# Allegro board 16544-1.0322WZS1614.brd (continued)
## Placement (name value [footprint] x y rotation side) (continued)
PC259  SC68P50V2JN-1GP  [C402H22]  139.19 74.17 90 top
PC260  SC10U6D3V3MX-DL-GP  [C603H36]  136.27 74.3 270 top
PC261  SC10U6D3V3MX-DL-GP  [C603H36]  136.27 75.56 270 top
PC262  SC1U50V3KX-1-GP  [C603H36]  130.53 128.19 270 top
PC263  SC10U6D3V3MX-DL-GP  [C603H36]  134.34 130.73 90 top
PC265  SC68P50V2JN-1GP  [C402H22]  141.07 128.83 90 top
PC266  SC10U6D3V3MX-DL-GP  [C603H36]  137.52 132 270 top
PC267  SC10U6D3V3MX-DL-GP  [C603H36]  137.52 130.73 270 top
PC268  SC1U50V3KX-1-GP  [C603H36]  122.43 200.91 270 top
PC269  SC1U10V2KX-1DLGP  [C402H22]  122.3 211.58 270 top
PC270  SC10U6D3V3MX-DL-GP  [C603H36]  122.43 210.44 270 top
PC271  SC10U6D3V3MX-DL-GP  [C603H36]  128.02 210.57 90 top
PC272  SC1U10V2KX-1DLGP  [C402H22]  124.33 214.12 270 top
PC274  SC4D7U6D3V3KX-DLGP  [C603H36]  113.02 150.09 90 bottom
PC275  SC4D7U6D3V3KX-DLGP  [C603H36]  111.91 154.46 270 top
PC276  SC1U10V2KX-1DLGP  [C402H22]  105.1 144.41 0 top
PC277  SCD1U25V2KX-1-DL-GP  [C402H22]  121.94 139.66 0 top
PC278  SCD01U50V2KX-1DLGP  [C402H22]  116.18 145.99 0 bottom
PC279  SCD22U25V3KX-DL-GP  [C603H36]  121.6 142.2 180 top
PC280  SCD22U25V3KX-DL-GP  [C603H36]  124.58 143.12 270 top
PC281  SCD1U25V2KX-1-DL-GP  [C402H22]  123.18 141.06 270 top
PC282  SCD22U25V3KX-DL-GP  [C603H36]  124.47 146.37 0 top
PC283  SCD1U25V2KX-1-DL-GP  [C402H22]  125.53 144.87 0 top
PC284  SCD22U25V3KX-DL-GP  [C603H36]  123.02 150.33 180 top
PC285  SCD1U25V2KX-1-DL-GP  [C402H22]  125.53 148.73 0 top
PC286  SCD1U25V2KX-1-DL-GP  [C402H22]  125.22 152.02 0 top
PC287  SC4700P50V2KX-1DLGP  [C402H22]  117.04 154.34 0 top
PC288  SCD22U25V3KX-DL-GP  [C603H36]  123.99 154.04 180 top
PC289  SCD1U25V2KX-1-DL-GP  [C402H22]  118.49 155.96 90 top
PC290  SCD1U25V2KX-1-DL-GP  [C402H22]  116.11 150.13 180 bottom
PC291  SCD1U25V2KX-1-DL-GP  [C402H22]  125.22 155.83 0 top
PC292  SCD22U25V3KX-DL-GP  [C603H36]  124.02 156.73 180 top
PC293  SCD1U25V2KX-1-DL-GP  [C402H22]  120.68 152.29 180 bottom
PC294  SCD22U25V3KX-DL-GP  [C603H36]  119.65 153.4 0 bottom
PC295  SC4700P50V2KX-1DLGP  [C402H22]  119.33 141.72 180 top
PC296  SCD1U25V2KX-1-DL-GP  [C402H22]  119.99 139.64 0 top
PC297  SCD1U25V2KX-1-DL-GP  [C402H22]  117.17 145.91 0 bottom
PC298  SC470P50V2KX-3DLGP  [C402H22]  115.65 154.58 90 bottom
PC299  SC470P50V2KX-3DLGP  [C402H22]  115.98 157.53 270 top
PC300  SC470P50V2KX-3DLGP  [C402H22]  112.01 151.18 270 bottom
PC301  SC470P50V2KX-3DLGP  [C402H22]  112.55 156.79 270 bottom
PC304  SC10U25V5KX-L-GP  [C805H56]  98.58 112.88 90 bottom
PC306  SC10U25V5KX-L-GP  [C805H56]  64.26 113.28 270 bottom
PC307  SC1U10V2KX-1DLGP  [C402H22]  95.66 120.73 90 bottom
PC308  SC1U10V2KX-1DLGP  [C402H22]  58.75 120.8 90 bottom
PC309  SCD22U25V3KX-DL-GP  [C603H36]  97.38 118.39 270 bottom
PC310  SC1KP50V2KX-1DLGP  [C402H22]  105.66 123.8 0 top
PC311  SCD22U25V3KX-DL-GP  [C603H36]  60.43 118.41 270 bottom
PC312  SC1KP50V2KX-1DLGP  [C402H22]  68.78 122.91 0 top
PC313  SC1U50V3KX-1-GP  [C603H36]  90.17 115.14 270 bottom
PC314  SC1U50V3KX-1-GP  [C603H36]  54.51 112.78 90 top
PC315  SC10U25V5KX-L-GP  [C805H56]  48.54 112.83 270 top
PC316  SC10U25V5KX-L-GP  [C805H56]  86.11 113.28 90 bottom
PC317  SC22U6D3V5MX-2DLGP  [C805H54]  92.46 148.79 270 bottom
PC318  SC22U6D3V5MX-2DLGP  [C805H54]  35.62 149.31 270 top
PC319  SC22U6D3V5MX-2DLGP  [C805H54]  35.62 147.25 270 top
PC320  SC22U6D3V5MX-2DLGP  [C805H54]  35.59 145.24 270 top
PC321  SC22U6D3V5MX-2DLGP  [C805H54]  83 152.65 270 bottom
PC322  SC22U6D3V5MX-2DLGP  [C805H54]  87.55 148.8 90 bottom
PC323  SC22U6D3V5MX-2DLGP  [C805H54]  87.56 152.69 90 bottom
PC324  SC22U6D3V5MX-2DLGP  [C805H54]  92.46 150.72 270 bottom
PC325  SC22U6D3V5MX-2DLGP  [C805H54]  83.01 150.64 270 bottom
PC326  SC22U6D3V5MX-2DLGP  [C805H54]  83.13 151.63 90 top
PC327  SC1U10V2KX-1DLGP  [C402H22]  84.15 120.98 90 bottom
PC328  SC1U10V2KX-1DLGP  [C402H22]  47.85 120.83 90 bottom
PC329  SCD22U25V3KX-DL-GP  [C603H36]  49.22 118.44 270 bottom
PC330  SCD22U25V3KX-DL-GP  [C603H36]  85.92 118.39 270 bottom
PC331  SC1KP50V2KX-1DLGP  [C402H22]  56.95 122.56 0 top
PC332  SC1KP50V2KX-1DLGP  [C402H22]  93.93 122.53 0 top
PC333  SC22U6D3V5MX-2DLGP  [C805H54]  83.13 153.61 90 top
PC334  SC22U6D3V5MX-2DLGP  [C805H54]  87.69 153.19 270 top
PC335  SC22U6D3V5MX-2DLGP  [C805H54]  87.69 151.26 270 top
PC336  SC22U6D3V5MX-2DLGP  [C805H54]  77.72 151.62 90 bottom
PC337  SC22U6D3V5MX-2DLGP  [C805H54]  83.13 147.7 90 top
PC338  SC22U6D3V5MX-2DLGP  [C805H54]  83.13 149.63 90 top
PC339  SC22U6D3V5MX-2DLGP  [C805H54]  87.68 149.31 270 top
PC340  SC22U6D3V5MX-2DLGP  [C805H54]  87.68 147.38 270 top
PC341  SC22U6D3V5MX-2DLGP  [C805H54]  77.65 152.05 270 top
PC342  SC22U6D3V5MX-2DLGP  [C805H54]  77.65 149.87 270 top
PC344  SC10U25V5KX-L-GP  [C805H56]  78.23 113.28 270 bottom
PC345  SC1U50V3KX-1-GP  [C603H36]  43 112.6 90 top
PC346  SC10U25V5KX-L-GP  [C805H56]  37.01 112.95 270 top
PC347  SC22U6D3V5MX-2DLGP  [C805H54]  77.65 147.71 270 top
PC348  SC22U6D3V5MX-2DLGP  [C805H54]  35.59 143.24 270 top
PC349  SC22U6D3V5MX-2DLGP  [C805H54]  35.59 141.31 270 top
PC350  SC22U6D3V5MX-2DLGP  [C805H54]  83.01 148.71 270 bottom
PC351  SC22U6D3V5MX-2DLGP  [C805H54]  87.55 150.73 90 bottom
PC352  SC22U6D3V5MX-2DLGP  [C805H54]  75.53 179.37 180 bottom
PC353  SC22U6D3V5MX-2DLGP  [C805H54]  92.46 147.64 90 top
PC354  SC22U6D3V5MX-2DLGP  [C805H54]  92.46 149.58 90 top
PC355  SC22U6D3V5MX-2DLGP  [C805H54]  92.46 151.51 90 top
PC356  SC22U6D3V5MX-2DLGP  [C805H54]  92.46 153.44 90 top
PC357  SC1U10V2KX-1DLGP  [C402H22]  72.28 119.79 0 top
PC358  SC1U10V2KX-1DLGP  [C402H22]  35.74 120.33 270 top
PC359  SCD22U25V3KX-DL-GP  [C603H36]  74.97 118.69 270 bottom
PC360  SCD22U25V3KX-DL-GP  [C603H36]  37.99 118.44 270 bottom
PC361  SC1KP50V2KX-1DLGP  [C402H22]  82.47 122.66 0 top
PC362  SC1KP50V2KX-1DLGP  [C402H22]  46.18 122.07 0 top
PC363  SC1U50V3KX-1-GP  [C603H36]  145.31 225.55 90 bottom
PC364  SC10U25V5KX-DL-GP  [C805H58]  145.19 223.9 90 bottom
PC365  SC1U10V2KX-1DLGP  [C402H22]  137.67 215.9 0 top
PC366  SC22U6D3V5MX-2DLGP  [C805H54]  116.31 214.88 0 top
PC367  SCD22U25V3KX-DL-GP  [C603H36]  137.08 215.98 180 bottom
PC368  SC22U6D3V5MX-2DLGP  [C805H54]  118.26 214.87 0 top
PC369  SC22U6D3V5MX-2DLGP  [C805H54]  118.57 218.83 180 bottom
PC370  SC22U6D3V5MX-2DLGP  [C805H54]  116.48 218.81 180 bottom
PC371  SC1KP50V2KX-1DLGP  [C402H22]  135.2 228.3 90 top
PC372  SC2D2U10V3KX-1DLGP-U  [C603H36]  119.51 204.17 270 bottom
PC373  SCD1U25V2KX-1-DL-GP  [C402H22]  112.83 202.59 0 bottom
PC374  SC1U10V2KX-1DLGP  [C402H22]  121.28 204.72 180 bottom
PC375  SC22U6D3V5MX-2DLGP  [C805H54]  119.96 194.97 270 bottom
PC376  SC22U6D3V5MX-2DLGP  [C805H54]  113.16 192.79 90 bottom
PC377  SC22U6D3V5MX-2DLGP  [C805H54]  119.91 196.95 270 bottom
PC378  SC22U6D3V5MX-2DLGP  [C805H54]  113.16 196.75 90 bottom
PC379  SC22U6D3V5MX-2DLGP  [C805H54]  113.16 194.82 90 bottom
PC380  SCD1U25V2KX-1-DL-GP  [C402H22]  111.1 206.07 270 top
PC381  SC10U25V5KX-DL-GP  [C805H58]  116.1 214.15 270 bottom
PC382  SC10U25V5KX-DL-GP  [C805H58]  110.31 205.08 90 bottom
PC383  SC470P50V2KX-3DLGP  [C402H22]  119.23 207.04 90 bottom
PC384  SC1U10V2KX-1DLGP  [C402H22]  14.55 210.67 90 top
PC385  SCD1U50V3KX-DL-GP  [C603H35]  10.82 215.98 0 top
PC386  SC22U6D3V5MX-2DLGP  [C805H54]  35.1 221.28 0 bottom
PC387  SC10U25V5KX-DL-GP  [C805H58]  13.61 218.44 180 bottom
PC388  SCD1U25V2KX-1-DL-GP  [C402H22]  15.6 223.6 0 bottom
PC389  SC22U6D3V5MX-2DLGP  [C805H54]  34.85 212.62 180 bottom
PC390  SC22U6D3V5MX-2DLGP  [C805H54]  31.34 212.62 0 top
PC391  SC22U6D3V5MX-2DLGP  [C805H54]  33.35 212.62 0 top
PC392  SC22U6D3V5MX-2DLGP  [C805H54]  33.12 221.28 0 bottom
PC393  SC22U6D3V5MX-2DLGP  [C805H54]  32.79 212.6 180 bottom
PC396  SC10U25V5KX-DL-GP  [C805H58]  15.6 218.44 180 bottom
PC397  SC18P50V2JN-1DLGP  [C402H22]  5.59 209.63 0 top
PC399  SC10U10V5KX-2DLGP  [C805H50]  135.71 23.37 0 bottom
PC400  SC10U10V5KX-2DLGP  [C805H50]  136.55 32.23 180 bottom
PC401  SC10U10V5KX-2DLGP  [C805H50]  130.56 32.23 180 bottom
PC405  SC22U6D3V5MX-2DLGP  [C805H54]  228.85 98.42 270 bottom
PC406  SC22U6D3V5MX-2DLGP  [C805H54]  228.85 100.46 270 bottom
PC407  SC22U6D3V5MX-2DLGP  [C805H54]  228.85 102.49 270 bottom
PC408  SC22U6D3V5MX-2DLGP  [C805H54]  228.85 104.52 270 bottom
PC409  SC4D7U6D3V3KX-DLGP  [C603H36]  106.17 144.19 0 top
PC410  SC22U6D3V5MX-2DLGP  [C805H54]  145.92 199.77 270 top
PC411  SC10U25V5KX-DL-GP  [C805H58]  153.16 224.51 90 top
PC412  SC10U25V5KX-DL-GP  [C805H58]  153.16 224.41 270 bottom
PC413  SC10U25V5KX-DL-GP  [C805H58]  13.61 218.44 0 top
PC414  SC10U25V5KX-DL-GP  [C805H58]  15.6 223.98 180 top
PC417  SC1U10V2KX-1DLGP  [C402H22]  142.19 216.92 0 bottom
PC418  SC1U50V3KX-1-GP  [C603H36]  135.33 208.03 180 top
PC419  SC10U6D3V3MX-DL-GP  [C603H36]  138.43 210.57 90 top
PC422  SC10U6D3V3MX-DL-GP  [C603H36]  145.8 208.79 180 top
PC423  SC10U6D3V3MX-DL-GP  [C603H36]  144.53 208.79 180 top
PC424  SC10U25V5KX-DL-GP  [C805H58]  112.14 17.17 180 top
PC425  SC10U25V5KX-DL-GP  [C805H58]  108.89 11.02 180 bottom
PC426  SCD1U25V2KX-1-DL-GP  [C402H22]  134.75 205.23 270 top
PC427  SC68P50V2JN-1GP  [C402H22]  144.53 204.98 0 top
PC428  SCD1U16V2KX-L-GP  [C402H22]  130.73 123.67 270 top
PC430  SCD47U25V3KX-1-DL-GP  [C603H36]  149.05 216.66 180 top
PC431  SCD47U25V3KX-1-DL-GP  [C603H36]  150.91 14.85 90 top
PC432  SCD1U16V2KX-L-GP  [C402H22]  142.98 64.82 0 top
PC433  SC1U50V3KX-1-GP  [C603H36]  138.73 65.2 90 top
PC437  SC10U25V5KX-DL-GP  [C805H58]  90.51 112.14 90 top
PC438  SC10U25V5KX-DL-GP  [C805H58]  90.49 110.14 90 top
PC439  SC10U25V5KX-DL-GP  [C805H58]  84.24 110.13 270 top
PC440  SC10U25V5KX-DL-GP  [C805H58]  84.24 112.14 270 top
PC456  SC1U50V3KX-1-GP  [C603H36]  107.4 160.31 90 top
PC457  SCD1U25V2KX-1-DL-GP  [C402H22]  106.99 164.63 90 top
PC458  SC10U6D3V3MX-DL-GP  [C603H36]  106.82 156.71 0 top
PC459  SC68P50V2JN-1GP  [C402H22]  95.85 160.84 180 top
PC460  SC10U6D3V3MX-DL-GP  [C603H36]  95.7 157.82 270 top
PC461  SC10U6D3V3MX-DL-GP  [C603H36]  95.7 159.25 270 top
PC484  SCD1U25V2KX-1-DL-GP  [C402H22]  139.19 107.31 270 bottom
PC485  SC10U6D3V3MX-DL-GP  [C603H36]  134.62 63.75 90 top
PC486  SC1U50V3KX-1-GP  [C603H36]  127.97 59.97 270 top
PC487  SCD1U25V2KX-1-DL-GP  [C402H22]  131.57 55.75 0 top
PC488  SC68P50V2JN-1GP  [C402H22]  137.56 59.94 0 top
PC489  SC10U6D3V3MX-DL-GP  [C603H36]  139.04 63.27 180 top
PC490  SC10U6D3V3MX-DL-GP  [C603H36]  137.77 63.27 180 top
PC491  SC10U25V5KX-DL-GP  [C805H58]  48.55 110.8 270 top
PC492  SC10U25V5KX-DL-GP  [C805H58]  53.66 113.21 270 bottom
PC493  SC10U25V5KX-DL-GP  [C805H58]  50.07 113.2 90 bottom
PC494  SC10U25V5KX-DL-GP  [C805H58]  54.7 111.22 90 top
PC495  SC10U25V5KX-DL-GP  [C805H58]  42.09 113.21 270 bottom
PC496  SC10U25V5KX-DL-GP  [C805H58]  43.17 110.99 90 top
PC497  SC10U25V5KX-DL-GP  [C805H58]  38.51 113.21 90 bottom
PC498  SC10U25V5KX-DL-GP  [C805H58]  37.02 110.95 270 top
PC499  SCD1U25V2KX-1-DL-GP  [C402H22]  116.82 210.77 0 bottom
PC500  SCD1U25V2KX-1-DL-GP  [C402H22]  9.06 206.71 90 bottom
PC501  SCD1U25V2KX-1-DL-GP  [C402H22]  105.15 161.65 270 bottom
PC502  SCD1U25V2KX-1-DL-GP  [C402H22]  113.19 145.98 0 bottom
PC503  SCD1U25V2KX-1-DL-GP  [C402H22]  100.26 35.54 180 top
PC504  SCD1U25V2KX-1-DL-GP  [C402H22]  99.95 25.78 270 top
PC505  SCD1U25V2KX-1-DL-GP  [C402H22]  6.6 196.35 0 bottom
PC506  SCD22U25V3KX-DL-GP  [C603H36]  218.97 212.75 0 bottom
PC507  SCD1U25V2KX-1-DL-GP  [C402H22]  105.89 142.34 270 top
PC508  SC10U25V5KX-DL-GP  [C805H58]  15.6 218.44 0 top
PC509  SC1500P50V2KX-2-DL-GP  [C402H22]  19.91 217.42 270 top
PC510  SCD047U25V2KX-4-GP  [C402H22]  8.15 211.94 0 bottom
PC511  SC1U10V2KX-1DLGP  [C402H22]  13.39 207.8 0 top
PCH1  PROM2-100-CG2774-GP  [BGA583D21H60]  161 45 0 top
PD1  CES520-GP  [SOD523AKH28]  215.44 36.5 270 top
PD2  CES520-GP  [SOD523AKH28]  215.44 35.02 270 top
PG5  GAP-CLOSE-PWR-3-GP  [GAP-CLOSE-PWR-3]  138.2 20.07 180 bottom
PG6  GAP-CLOSE-PWR-3-GP  [GAP-CLOSE-PWR-3]  138.2 19.3 0 bottom
PG7  GAP-CLOSE-PWR-3-GP  [GAP-CLOSE-PWR-3]  107.19 13.84 0 bottom
PG8  GAP-CLOSE-PWR-3-GP  [GAP-CLOSE-PWR-3]  106.96 37.62 0 bottom
PG9  GAP-CLOSE-PWR-3-GP  [GAP-CLOSE-PWR-3]  138.33 36.53 180 top
PG10  GAP-CLOSE-PWR-3-GP  [GAP-CLOSE-PWR-3]  138.33 37.29 0 top
PG11  GAP-CLOSE-PWR-3-GP  [GAP-CLOSE-PWR-3]  138.2 21.59 180 bottom
PG12  GAP-CLOSE-PWR-3-GP  [GAP-CLOSE-PWR-3]  138.2 20.83 0 bottom
PG13  GAP-CLOSE-PWR-3-GP  [GAP-CLOSE-PWR-3]  107.19 12.32 0 bottom
PG14  GAP-CLOSE-PWR-3-GP  [GAP-CLOSE-PWR-3]  106.96 38.38 0 bottom
PG15  GAP-CLOSE-PWR-3-GP  [GAP-CLOSE-PWR-3]  138.33 35.76 180 top
PG16  GAP-CLOSE-PWR-3-GP  [GAP-CLOSE-PWR-3]  138.33 32.72 0 bottom
PG17  GAP-CLOSE-PWR-3-GP  [GAP-CLOSE-PWR-3]  138.2 19.3 180 top
PG18  GAP-CLOSE-PWR-3-GP  [GAP-CLOSE-PWR-3]  138.2 20.07 0 top
PG19  GAP-CLOSE-PWR-3-GP  [GAP-CLOSE-PWR-3]  107.19 13.08 0 bottom
PG20  GAP-CLOSE-PWR-3-GP  [GAP-CLOSE-PWR-3]  106.96 39.9 0 bottom
PG21  GAP-CLOSE-PWR-3-GP  [GAP-CLOSE-PWR-3]  138.33 36.53 180 bottom
PG22  GAP-CLOSE-PWR-3-GP  [GAP-CLOSE-PWR-3]  138.33 35 0 top
PG23  GAP-CLOSE-PWR-3-GP  [GAP-CLOSE-PWR-3]  106.96 39.14 0 bottom
PG24  GAP-CLOSE-PWR-3-GP  [GAP-CLOSE-PWR-3]  138.2 20.83 180 top
PG25  GAP-CLOSE-PWR-3-GP  [GAP-CLOSE-PWR-3]  138.33 35.76 180 bottom
PG26  GAP-CLOSE-PWR-3-GP  [GAP-CLOSE-PWR-3]  138.33 34.24 0 bottom
PG27  GAP-CLOSE-PWR-3-GP  [GAP-CLOSE-PWR-3]  138.2 21.59 0 top
PG28  GAP-CLOSE-PWR-3-GP  [GAP-CLOSE-PWR-3]  106.96 36.86 0 bottom
PG29  GAP-CLOSE-PWR-3-GP  [GAP-CLOSE-PWR-3]  138.33 35 180 bottom
PG30  GAP-CLOSE-PWR-3-GP  [GAP-CLOSE-PWR-3]  138.33 34.24 0 top
PG31  GAP-CLOSE-PWR-3-GP  [GAP-CLOSE-PWR-3]  138.2 18.54 180 bottom
PG32  GAP-CLOSE-PWR-3-GP  [GAP-CLOSE-PWR-3]  138.2 18.54 0 top
PG33  GAP-CLOSE-PWR-3-GP  [GAP-CLOSE-PWR-3]  130.33 16.87 90 bottom
PG34  GAP-CLOSE-PWR-3-GP  [GAP-CLOSE-PWR-3]  132.56 39.04 270 bottom
PG35  GAP-CLOSE-PWR-3-GP  [GAP-CLOSE-PWR-3]  133.58 39.04 270 bottom
PG36  GAP-CLOSE-PWR-3-GP  [GAP-CLOSE-PWR-3]  96.01 30.73 90 top
PG38  GAP-CLOSE-PWR-3-GP  [GAP-CLOSE-PWR-3]  191.06 228.14 270 top
PG39  GAP-CLOSE-PWR-3-GP  [GAP-CLOSE-PWR-3]  190.3 228.14 270 top
PG40  GAP-CLOSE-PWR-3-GP  [GAP-CLOSE-PWR-3]  189.54 228.14 270 top
PG41  GAP-CLOSE-PWR-3-GP  [GAP-CLOSE-PWR-3]  198.73 204.39 180 top
PG42  GAP-CLOSE-PWR-3-GP  [GAP-CLOSE-PWR-3]  192.89 204.42 0 top
PG43  GAP-CLOSE-PWR-3-GP  [GAP-CLOSE-PWR-3]  175.31 229.44 270 top
PG44  GAP-CLOSE-PWR-3-GP  [GAP-CLOSE-PWR-3]  173.79 229.44 270 top
PG45  GAP-CLOSE-PWR-3-GP  [GAP-CLOSE-PWR-3]  174.55 229.44 270 top
PG46  GAP-CLOSE-PWR-3-GP  [GAP-CLOSE-PWR-3]  181.79 205.71 180 top
PG47  GAP-CLOSE-PWR-3-GP  [GAP-CLOSE-PWR-3]  176.02 205.71 0 top
PG48  GAP-CLOSE-PWR-3-GP  [GAP-CLOSE-PWR-3]  159.69 229.24 270 top
PG49  GAP-CLOSE-PWR-3-GP  [GAP-CLOSE-PWR-3]  160.45 229.24 270 top
PG50  GAP-CLOSE-PWR-3-GP  [GAP-CLOSE-PWR-3]  158.93 229.24 270 top
PG51  GAP-CLOSE-PWR-3-GP  [GAP-CLOSE-PWR-3]  159.82 205.46 0 top
PG52  GAP-CLOSE-PWR-3-GP  [GAP-CLOSE-PWR-3]  165.63 205.61 180 top
PG53  GAP-CLOSE-PWR-3-GP  [GAP-CLOSE-PWR-3]  218.31 198.83 270 top
PG54  GAP-CLOSE-PWR-3-GP  [GAP-CLOSE-PWR-3]  219.07 198.83 270 top
PG55  GAP-CLOSE-PWR-3-GP  [GAP-CLOSE-PWR-3]  217.55 198.83 270 top
PG56  GAP-CLOSE-PWR-3-GP  [GAP-CLOSE-PWR-3]  214.07 177.16 270 top
PG57  GAP-CLOSE-PWR-3-GP  [GAP-CLOSE-PWR-3]  214.22 171.4 90 top
PG58  GAP-CLOSE-PWR-3-GP  [GAP-CLOSE-PWR-3]  226.62 201.8 270 top
PG59  GAP-CLOSE-PWR-3-GP  [GAP-CLOSE-PWR-3]  227.38 201.8 270 top
PG60  GAP-CLOSE-PWR-3-GP  [GAP-CLOSE-PWR-3]  228.14 201.8 270 top
PG61  GAP-CLOSE-PWR-3-GP  [GAP-CLOSE-PWR-3]  226.29 177.19 270 top
PG62  GAP-CLOSE-PWR-3-GP  [GAP-CLOSE-PWR-3]  226.42 171.42 90 top
PG63  GAP-CLOSE-PWR-3-GP  [GAP-CLOSE-PWR-3]  231.65 130.94 180 top
PG64  GAP-CLOSE-PWR-3-GP  [GAP-CLOSE-PWR-3]  231.65 130.18 180 top
PG65  GAP-CLOSE-PWR-3-GP  [GAP-CLOSE-PWR-3]  222.63 104.78 180 bottom
PG66  GAP-CLOSE-PWR-3-GP  [GAP-CLOSE-PWR-3]  231.65 129.41 180 top
PG67  GAP-CLOSE-PWR-3-GP  [GAP-CLOSE-PWR-3]  222.63 99.44 180 bottom
PG68  GAP-CLOSE-PWR-3-GP  [GAP-CLOSE-PWR-3]  222.63 100.2 180 bottom
PG69  GAP-CLOSE-PWR-3-GP  [GAP-CLOSE-PWR-3]  222.63 100.97 180 bottom
PG70  GAP-CLOSE-PWR-3-GP  [GAP-CLOSE-PWR-3]  222.63 101.73 180 bottom
PG71  GAP-CLOSE-PWR-3-GP  [GAP-CLOSE-PWR-3]  222.63 102.49 180 bottom
PG72  GAP-CLOSE-PWR-3-GP  [GAP-CLOSE-PWR-3]  226.62 134.65 90 top
PG73  GAP-CLOSE-PWR-3-GP  [GAP-CLOSE-PWR-3]  222.63 104.01 180 bottom
PG74  GAP-CLOSE-PWR-3-GP  [GAP-CLOSE-PWR-3]  227.38 134.65 90 top
PG75  GAP-CLOSE-PWR-3-GP  [GAP-CLOSE-PWR-3]  222.63 99.44 180 top
PG76  GAP-CLOSE-PWR-3-GP  [GAP-CLOSE-PWR-3]  222.63 100.2 180 top
PG77  GAP-CLOSE-PWR-3-GP  [GAP-CLOSE-PWR-3]  222.63 105 0 top
PG78  GAP-CLOSE-PWR-3-GP  [GAP-CLOSE-PWR-3]  222.63 100.97 180 top
PG79  GAP-CLOSE-PWR-3-GP  [GAP-CLOSE-PWR-3]  222.63 101.73 180 top
PG80  GAP-CLOSE-PWR-3-GP  [GAP-CLOSE-PWR-3]  228.4 136.6 90 top
PG81  GAP-CLOSE-PWR-3-GP  [GAP-CLOSE-PWR-3]  222.63 102.49 180 top
PG82  GAP-CLOSE-PWR-3-GP  [GAP-CLOSE-PWR-3]  229.16 136.6 90 top
PG83  GAP-CLOSE-PWR-3-GP  [GAP-CLOSE-PWR-3]  222.63 98.68 180 bottom
PG84  GAP-CLOSE-PWR-3-GP  [GAP-CLOSE-PWR-3]  222.63 104.01 180 top
PG85  GAP-CLOSE-PWR-3-GP  [GAP-CLOSE-PWR-3]  222.63 98.68 180 top
PG86  GAP-CLOSE-PWR-3-GP  [GAP-CLOSE-PWR-3]  222.63 103.25 180 top
PG87  GAP-CLOSE-PWR-3-GP  [GAP-CLOSE-PWR-3]  222.63 103.25 180 bottom
PG106  GAP-CLOSE-PWR-3-GP  [GAP-CLOSE-PWR-3]  151.2 226.29 270 top
PG107  GAP-CLOSE-PWR-3-GP  [GAP-CLOSE-PWR-3]  150.53 199.03 270 top
PG108  GAP-CLOSE-PWR-3-GP  [GAP-CLOSE-PWR-3]  151.29 199.03 270 top
PG109  GAP-CLOSE-PWR-3-GP  [GAP-CLOSE-PWR-3]  152.72 226.29 270 top
PG110  GAP-CLOSE-PWR-3-GP  [GAP-CLOSE-PWR-3]  146.94 198.25 0 top
PG111  GAP-CLOSE-PWR-3-GP  [GAP-CLOSE-PWR-3]  149.77 199.03 270 top
PG112  GAP-CLOSE-PWR-3-GP  [GAP-CLOSE-PWR-3]  151.96 226.29 270 top
PG113  GAP-CLOSE-PWR-3-GP  [GAP-CLOSE-PWR-3]  149.01 199.03 270 top
PG114  GAP-CLOSE-PWR-3-GP  [GAP-CLOSE-PWR-3]  148.27 199.02 270 bottom
PG115  GAP-CLOSE-PWR-3-GP  [GAP-CLOSE-PWR-3]  148.24 199.03 270 top
PG116  GAP-CLOSE-PWR-3-GP  [GAP-CLOSE-PWR-3]  149.03 199.02 270 bottom
PG117  GAP-CLOSE-PWR-3-GP  [GAP-CLOSE-PWR-3]  149.79 199.02 270 bottom
PG118  GAP-CLOSE-PWR-3-GP  [GAP-CLOSE-PWR-3]  151.32 199.02 270 bottom
PG119  GAP-CLOSE-PWR-3-GP  [GAP-CLOSE-PWR-3]  150.56 199.02 270 bottom
PG120  GAP-CLOSE-PWR-3-GP  [GAP-CLOSE-PWR-3]  147.55 32.86 180 top
PG121  GAP-CLOSE-PWR-3-GP  [GAP-CLOSE-PWR-3]  147.18 10.88 180 top
PG122  GAP-CLOSE-PWR-3-GP  [GAP-CLOSE-PWR-3]  147.18 10.12 180 top
PG123  GAP-CLOSE-PWR-3-GP  [GAP-CLOSE-PWR-3]  145.03 34.09 90 top
PG124  GAP-CLOSE-PWR-3-GP  [GAP-CLOSE-PWR-3]  144.27 34.09 90 top
PG125  GAP-CLOSE-PWR-3-GP  [GAP-CLOSE-PWR-3]  147.18 9.36 180 top
PG126  GAP-CLOSE-PWR-3-GP  [GAP-CLOSE-PWR-3]  145.8 34.09 90 top
PG127  GAP-CLOSE-PWR-3-GP  [GAP-CLOSE-PWR-3]  146.56 34.09 90 top
PG129  GAP-CLOSE-PWR-3-GP  [GAP-CLOSE-PWR-3]  143.51 34.09 90 top
PG131  GAP-CLOSE-PWR-3-GP  [GAP-CLOSE-PWR-3]  129.39 107.04 0 top
PG132  GAP-CLOSE-PWR-3-GP  [GAP-CLOSE-PWR-3]  137.87 122.45 180 top
PG133  GAP-CLOSE-PWR-3-GP  [GAP-CLOSE-PWR-3]  129.39 107.8 0 top
PG134  GAP-CLOSE-PWR-3-GP  [GAP-CLOSE-PWR-3]  133.25 122.89 90 top
PG135  GAP-CLOSE-PWR-3-GP  [GAP-CLOSE-PWR-3]  134.01 122.89 90 top
PG136  GAP-CLOSE-PWR-3-GP  [GAP-CLOSE-PWR-3]  129.39 108.56 0 top
PG137  GAP-CLOSE-PWR-3-GP  [GAP-CLOSE-PWR-3]  132.49 122.89 90 top
PG138  GAP-CLOSE-PWR-3-GP  [GAP-CLOSE-PWR-3]  134.77 122.89 90 top
PG141  GAP-CLOSE-PWR-3-GP  [GAP-CLOSE-PWR-3]  135.53 122.89 90 top
PG142  GAP-CLOSE-PWR-3-GP  [GAP-CLOSE-PWR-3]  136.3 122.89 90 top
PG143  GAP-CLOSE-PWR-3-GP  [GAP-CLOSE-PWR-3]  12.09 204.9 0 bottom
PG144  GAP-CLOSE-PWR-3-GP  [GAP-CLOSE-PWR-3]  12.09 204.14 0 bottom
PG145  -  [0R0603-PAD]  10.41 183.26 0 top
PG146  -  [0R0603-PAD]  11.84 183.26 0 top
PG147  GAP-CLOSE-PWR-3-GP  [GAP-CLOSE-PWR-3]  134.24 68.81 180 top
PG148  GAP-CLOSE-PWR-3-GP  [GAP-CLOSE-PWR-3]  139.19 77.09 0 top
PG149  GAP-CLOSE-PWR-3-GP  [GAP-CLOSE-PWR-3]  139.19 76.33 0 top
PG150  GAP-CLOSE-PWR-3-GP  [GAP-CLOSE-PWR-3]  133.83 132.26 90 top
PG151  GAP-CLOSE-PWR-3-GP  [GAP-CLOSE-PWR-3]  139.88 132.46 90 top
PG152  GAP-CLOSE-PWR-3-GP  [GAP-CLOSE-PWR-3]  140.64 132.46 90 top
PG153  GAP-CLOSE-PWR-3-GP  [GAP-CLOSE-PWR-3]  122.81 213.87 90 top
PG154  GAP-CLOSE-PWR-3-GP  [GAP-CLOSE-PWR-3]  127.25 211.86 90 top
PG155  GAP-CLOSE-PWR-3-GP  [GAP-CLOSE-PWR-3]  97.87 105.84 90 top
PG156  GAP-CLOSE-PWR-3-GP  [GAP-CLOSE-PWR-3]  59.64 109.25 90 top
PG157  GAP-CLOSE-PWR-3-GP  [GAP-CLOSE-PWR-3]  97.1 105.84 90 top
PG158  GAP-CLOSE-PWR-3-GP  [GAP-CLOSE-PWR-3]  58.88 109.25 90 top
PG159  GAP-CLOSE-PWR-3-GP  [GAP-CLOSE-PWR-3]  96.34 105.84 90 top
PG160  GAP-CLOSE-PWR-3-GP  [GAP-CLOSE-PWR-3]  58.12 109.25 90 top
PG161  GAP-CLOSE-PWR-6-GP  [GAP-CLOSE-PWR]  99.95 128.66 270 top
PG162  GAP-CLOSE-PWR-6-GP  [GAP-CLOSE-PWR]  99.8 134.69 90 top
PG163  GAP-CLOSE-PWR-6-GP  [GAP-CLOSE-PWR]  62.81 128.73 270 top
PG164  GAP-CLOSE-PWR-6-GP  [GAP-CLOSE-PWR]  62.81 134.72 90 top
PG165  GAP-CLOSE-PWR-3-GP  [GAP-CLOSE-PWR-3]  86.54 109.15 90 top
PG166  GAP-CLOSE-PWR-3-GP  [GAP-CLOSE-PWR-3]  52.37 110.21 90 top
PG167  GAP-CLOSE-PWR-3-GP  [GAP-CLOSE-PWR-3]  87.43 109.15 90 top
PG168  GAP-CLOSE-PWR-3-GP  [GAP-CLOSE-PWR-3]  50.85 110.21 90 top
PG169  GAP-CLOSE-PWR-3-GP  [GAP-CLOSE-PWR-3]  88.19 109.15 90 top
PG170  GAP-CLOSE-PWR-3-GP  [GAP-CLOSE-PWR-3]  51.61 110.21 90 top
PG171  GAP-CLOSE-PWR-6-GP  [GAP-CLOSE-PWR]  88.32 128.66 270 top
PG172  GAP-CLOSE-PWR-6-GP  [GAP-CLOSE-PWR]  88.29 134.61 90 top
PG173  GAP-CLOSE-PWR-6-GP  [GAP-CLOSE-PWR]  51.66 128.71 270 top
PG174  GAP-CLOSE-PWR-6-GP  [GAP-CLOSE-PWR]  51.66 134.69 90 top
PG175  GAP-CLOSE-PWR-3-GP  [GAP-CLOSE-PWR-3]  40.11 110.01 90 top
PG176  GAP-CLOSE-PWR-3-GP  [GAP-CLOSE-PWR-3]  70.15 109.45 90 top
PG177  GAP-CLOSE-PWR-3-GP  [GAP-CLOSE-PWR-3]  40.87 110.01 90 top
PG178  GAP-CLOSE-PWR-3-GP  [GAP-CLOSE-PWR-3]  71.68 109.45 90 top
PG179  GAP-CLOSE-PWR-3-GP  [GAP-CLOSE-PWR-3]  39.34 110.01 90 top
PG180  GAP-CLOSE-PWR-3-GP  [GAP-CLOSE-PWR-3]  70.92 109.45 90 top
PG181  GAP-CLOSE-PWR-6-GP  [GAP-CLOSE-PWR]  77.19 128.66 270 top
PG182  GAP-CLOSE-PWR-6-GP  [GAP-CLOSE-PWR]  77.32 134.69 90 top
PG183  GAP-CLOSE-PWR-6-GP  [GAP-CLOSE-PWR]  40.64 128.68 270 top
PG184  GAP-CLOSE-PWR-6-GP  [GAP-CLOSE-PWR]  40.64 134.72 90 top
PG185  GAP-CLOSE-PWR-3-GP  [GAP-CLOSE-PWR-3]  148.16 227.29 270 bottom
PG186  GAP-CLOSE-PWR-3-GP  [GAP-CLOSE-PWR-3]  147.4 227.28 270 bottom
PG187  GAP-CLOSE-PWR-3-GP  [GAP-CLOSE-PWR-3]  146.63 227.28 270 bottom
PG188  GAP-CLOSE-PWR-6-GP  [GAP-CLOSE-PWR]  129.26 223.29 0 top
PG189  GAP-CLOSE-PWR-6-GP  [GAP-CLOSE-PWR]  123.22 223.19 180 top
PG190  GAP-CLOSE-PWR-3-GP  [GAP-CLOSE-PWR-3]  119.74 192.66 180 bottom
PG191  GAP-CLOSE-PWR-3-GP  [GAP-CLOSE-PWR-3]  113.94 216.15 270 bottom
PG192  GAP-CLOSE-PWR-3-GP  [GAP-CLOSE-PWR-3]  116.49 192.2 270 top
PG193  GAP-CLOSE-PWR-3-GP  [GAP-CLOSE-PWR-3]  118.02 192.2 270 top
PG194  GAP-CLOSE-PWR-3-GP  [GAP-CLOSE-PWR-3]  114.71 216.15 270 bottom
PG195  GAP-CLOSE-PWR-3-GP  [GAP-CLOSE-PWR-3]  115.6 192.2 270 top
PG196  GAP-CLOSE-PWR-3-GP  [GAP-CLOSE-PWR-3]  117.26 192.2 270 top
PG197  GAP-CLOSE-PWR-3-GP  [GAP-CLOSE-PWR-3]  11.73 221.58 0 bottom
PG198  GAP-CLOSE-PWR-3-GP  [GAP-CLOSE-PWR-3]  37.34 215.51 0 bottom
PG199  GAP-CLOSE-PWR-3-GP  [GAP-CLOSE-PWR-3]  37.34 214.75 0 bottom
PG201  GAP-CLOSE-PWR-3-GP  [GAP-CLOSE-PWR-3]  11.73 220.69 0 bottom
PG202  GAP-CLOSE-PWR-3-GP  [GAP-CLOSE-PWR-3]  37.34 220.08 0 bottom
PG203  GAP-CLOSE-PWR-3-GP  [GAP-CLOSE-PWR-3]  37.34 216.27 0 bottom
PG204  GAP-CLOSE-PWR-3-GP  [GAP-CLOSE-PWR-3]  11.73 219.8 0 bottom
PG205  GAP-CLOSE-PWR-3-GP  [GAP-CLOSE-PWR-3]  37.34 217.79 0 bottom
PG206  GAP-CLOSE-PWR-3-GP  [GAP-CLOSE-PWR-3]  37.34 218.56 0 bottom
PG207  GAP-CLOSE-PWR-3-GP  [GAP-CLOSE-PWR-3]  37.34 217.03 0 bottom
PG209  GAP-CLOSE-PWR-3-GP  [GAP-CLOSE-PWR-3]  148.26 99.92 90 bottom
PG210  GAP-CLOSE-PWR-3-GP  [GAP-CLOSE-PWR-3]  149.02 99.92 90 bottom
PG211  GAP-CLOSE-PWR-3-GP  [GAP-CLOSE-PWR-3]  138.2 22.35 0 top
PG212  GAP-CLOSE-PWR-3-GP  [GAP-CLOSE-PWR-3]  134.24 68.05 180 top
PG213  GAP-CLOSE-PWR-3-GP  [GAP-CLOSE-PWR-3]  138.33 33.48 0 bottom
PG214  GAP-CLOSE-PWR-3-GP  [GAP-CLOSE-PWR-3]  138.33 37.29 180 bottom
PG215  GAP-CLOSE-PWR-3-GP  [GAP-CLOSE-PWR-3]  138.05 211.96 0 top
PG220  GAP-CLOSE-PWR-3-GP  [GAP-CLOSE-PWR-3]  108.57 158.17 0 top
PG221  GAP-CLOSE-PWR-3-GP  [GAP-CLOSE-PWR-3]  108.55 157.16 0 top
PG222  GAP-CLOSE-PWR-3-GP  [GAP-CLOSE-PWR-3]  95.06 155.77 180 top
PG223  GAP-CLOSE-PWR-3-GP  [GAP-CLOSE-PWR-3]  95.08 156.66 180 top
PG224  GAP-CLOSE-PWR-3-GP  [GAP-CLOSE-PWR-3]  132.79 64.57 90 top
PG225  GAP-CLOSE-PWR-3-GP  [GAP-CLOSE-PWR-3]  132.03 64.57 90 top
PG226  GAP-CLOSE-PWR-3-GP  [GAP-CLOSE-PWR-3]  140.39 61.65 0 top
PG227  GAP-CLOSE-PWR-3-GP  [GAP-CLOSE-PWR-3]  140.39 62.41 0 top
PG228  GAP-CLOSE-PWR-6-GP  [GAP-CLOSE-PWR]  100.75 124.42 180 bottom
PG229  GAP-CLOSE-PWR-6-GP  [GAP-CLOSE-PWR]  133.73 218.82 0 top
PG230  GAP-CLOSE-PWR-3-GP  [GAP-CLOSE-PWR-3]  138.2 22.35 180 bottom
PG231  GAP-CLOSE-PWR-3-GP  [GAP-CLOSE-PWR-3]  138.2 23.11 180 bottom
PG232  GAP-CLOSE-PWR-3-GP  [GAP-CLOSE-PWR-3]  138.33 32.72 180 top
PG233  GAP-CLOSE-PWR-3-GP  [GAP-CLOSE-PWR-3]  138.33 33.48 0 top
PG234  GAP-CLOSE-PWR-3-GP  [GAP-CLOSE-PWR-3]  138.2 23.11 0 top
PG235  GAP-CLOSE-PWR-3-GP  [GAP-CLOSE-PWR-3]  131.27 64.57 90 top
PG236  GAP-CLOSE-PWR-3-GP  [GAP-CLOSE-PWR-3]  140.39 60.88 0 top
PG237  GAP-CLOSE-PWR-3-GP  [GAP-CLOSE-PWR-3]  35.04 212.37 90 top
PG238  GAP-CLOSE-PWR-3-GP  [GAP-CLOSE-PWR-3]  37.34 218.4 0 top
PG239  GAP-CLOSE-PWR-3-GP  [GAP-CLOSE-PWR-3]  37.34 217.64 0 top
PG240  GAP-CLOSE-PWR-3-GP  [GAP-CLOSE-PWR-3]  37.34 216.87 0 top
PG241  GAP-CLOSE-PWR-3-GP  [GAP-CLOSE-PWR-3]  37.34 216.11 0 top
PG242  GAP-CLOSE-PWR-3-GP  [GAP-CLOSE-PWR-3]  37.34 215.35 0 top
PG243  GAP-CLOSE-PWR-3-GP  [GAP-CLOSE-PWR-3]  37.34 214.59 0 top
PG244  GAP-CLOSE-PWR-3-GP  [GAP-CLOSE-PWR-3]  37.34 219.16 0 top
PG245  GAP-CLOSE-PWR-3-GP  [GAP-CLOSE-PWR-3]  37.34 213.83 0 top
PG246  GAP-CLOSE-PWR-3-GP  [GAP-CLOSE-PWR-3]  37.34 219.32 0 bottom
PG247  GAP-CLOSE-PWR-3-GP  [GAP-CLOSE-PWR-3]  37.34 213.98 0 bottom
PL1  IND-1D5UH-150-GP  [L109100-2030H138]  123.06 20.47 270 top
PL2  IND-1D5UH-150-GP  [L109100-2030H138]  123.06 34.04 90 top
PL3  IND-D36UH-58-GP  [L112100-2135H158]  195.8 205.52 90 top
PL4  IND-D36UH-58-GP  [L112100-2135H158]  178.93 205.5 90 top
PL5  IND-D36UH-58-GP  [L112100-2135H158]  162.72 205.53 90 top
PL6  IND-D36UH-58-GP  [L112100-2135H158]  214.12 174.24 0 top
PL7  IND-D36UH-58-GP  [L112100-2135H158]  226.29 174.27 0 top
PL8  IND-D56UH-42-GP  [L112100-2135H158]  227.33 112.24 0 top
PL10  IND-1UH-94-GP-U  [L686647-127318H119]  150.9 206.88 270 top
PL11  IND-1UH-94-GP-U  [L686647-127318H119]  145.39 24.62 180 top
PL12  IND-1UH-94-GP-U  [L686647-127318H119]  134.47 115.49 180 top
PL13  IND-6D8UH-134-GP  [L686647-127318H119]  10.46 190.5 180 bottom
PL14  IND-D15UH-13-GP  [L112100-2030H158]  99.39 131.67 180 top
PL15  IND-D15UH-13-GP  [L112100-2030H158]  62.74 131.7 180 top
PL16  IND-D15UH-13-GP  [L112100-2030H158]  88.24 131.67 180 top
PL17  IND-D15UH-13-GP  [L112100-2030H158]  51.61 131.7 180 top
PL18  IND-D15UH-13-GP  [L112100-2030H158]  77.14 131.67 180 top
PL19  IND-D15UH-13-GP  [L112100-2030H158]  40.51 131.7 180 top
PL20  IND-D15UH-13-GP  [L112100-2030H158]  126.24 223.27 270 top
PL21  IND-1UH-94-GP-U  [L686647-127318H119]  117.07 199.03 0 top
PL22  IND-D47UH-22-GP-U  [L7066-1830-UH119]  27.13 217.32 270 bottom
PMBUS1  JWT-CON3-S19-GP  [A2003WV0-1X3PA-6T]  124.79 122.1 90 top
PQ2  2N7002K-2-GP  [SOT23DGS2D4H44]  16.54 143.36 90 top
PQ3  SM4378NSKPC-TRG-GP  [PPAK-8PH48]  228.35 124.71 0 top
PQ4  SM4378NSKPC-TRG-GP  [PPAK-8PH48]  228.35 124.71 180 bottom
PQ5  SM4504NHKPC-TRG-1-GP  [PPAK-8PH48]  219.79 122.94 180 top
PQ6  SM4504NHKPC-TRG-1-GP  [PPAK-8PH48]  219.79 122.94 0 bottom
PQ9  MMBT3906-6-GP  [SOT23CBE2D4H44]  106.86 136.5 270 top
PQ10  MMBT3906-6-GP  [SOT23CBE2D4H44]  130.96 215.9 90 top
PQ11  2N7002KDW-1-GP  [SOT-363H44]  127.13 214.38 90 top
PQ12  2N7002K-2-GP  [SOT23DGS2D4H44]  14.39 141.58 90 bottom
PR1  10KR2F-2-GP  [R402H16]  216.36 37.66 270 top
PR2  8D2R2J-GP  [R402H16]  219.71 37.08 0 bottom
PR3  8D2R2J-GP  [R402H16]  222.63 43.31 90 bottom
PR4  40K2R2F-GP  [R402H16]  206.38 25.63 90 top
PR5  40K2R2F-GP  [R402H16]  206.13 26.67 90 top
PR6  40K2R2F-GP  [R402H16]  206.65 29.74 90 top
PR7  40K2R2F-GP  [R402H16]  207.26 31.19 0 top
PR8  40K2R2F-GP  [R402H16]  208.33 31.18 180 bottom
PR9  40K2R2F-GP  [R402H16]  210.57 31.72 0 top
PR10  10KR2F-2-GP  [R402H16]  206.13 24.61 90 top
PR11  10KR2F-2-GP  [R402H16]  208.33 31.17 180 top
PR12  10KR2F-2-GP  [R402H16]  206.13 27.68 90 top
PR13  10KR2F-2-GP  [R402H16]  209.37 31.18 0 bottom
PR14  10KR2F-2-GP  [R402H16]  206.11 28.72 90 top
PR15  10KR2F-2-GP  [R402H16]  209.48 31.18 180 top
PR16  10KR2F-2-GP  [R402H16]  214.32 31.17 270 top
PR17  10KR2F-2-GP  [R402H16]  214.31 32.2 90 top
PR18  40K2R2F-GP  [R402H16]  188.52 24.28 90 top
PR19  40K2R2F-GP  [R402H16]  188.65 26.34 90 top
PR20  40K2R2F-GP  [R402H16]  189.03 28.37 90 top
PR21  40K2R2F-GP  [R402H16]  189 31.54 90 top
PR22  40K2R2F-GP  [R402H16]  190.47 31.34 0 top
PR23  40K2R2F-GP  [R402H16]  193.62 31.45 0 top
PR24  10KR2F-2-GP  [R402H16]  188.65 25.32 90 top
PR25  10KR2F-2-GP  [R402H16]  189 30.46 270 top
PR26  10KR2F-2-GP  [R402H16]  188.65 27.35 90 top
PR27  10KR2F-2-GP  [R402H16]  191.49 31.34 180 top
PR28  10KR2F-2-GP  [R402H16]  186.74 28.88 90 top
PR29  10KR2F-2-GP  [R402H16]  192.53 32.29 180 top
PR30  10KR2F-2-GP  [R402H16]  198.04 33.25 0 top
PR31  10KR2F-2-GP  [R402H16]  197 31.7 180 top
PR50  100KR2F-L1-GP  [R402H16]  16.87 142.32 180 bottom
PR53  2D2R3-1-U-GP  [R603H22]  104.98 25.4 180 top
PR54  2D2R3-1-U-GP  [R603H22]  105.69 36.63 180 top
PR55  2D2R5F-2-GP  [R805H24]  118.26 18.26 90 bottom
PR56  2D2R5F-2-GP  [R805H24]  118.64 33.83 90 bottom
PR57  63K4R2F-2-GP  [R402H16]  98.48 26.39 0 top
PR58  66K5R2F-GP  [R402H16]  96.88 34.39 270 top
PR59  6K8R2F-2-GP  [R402H16]  96.29 26.77 180 top
PR60  15K4R2F-GP  [R402H16]  96.88 32.23 90 top
PR61  10KR2F-2-GP  [R402H16]  97.41 27.05 0 top
PR62  10KR2F-2-GP  [R402H16]  96.88 33.25 270 top
PR63  10KR2F-2-GP  [R402H16]  99.75 23.57 90 top
PR64  10KR2F-2-GP  [R402H16]  102.57 23.06 180 top
PR65  0R0402-PAD-1-GP  [0R0402-PAD]  101.47 25.27 0 top
PR66  0R0402-PAD-2-GP  [0R0402-PAD-1]  99.29 35.53 0 top
PR67  0R0402-PAD-2-GP  [0R0402-PAD-1]  99.95 24.77 90 top
PR68  8K2R2F-1-GP  [R402H16]  215.37 230.35 270 bottom
PR69  2K8R2F-GP  [R402H16]  217.3 227.13 90 bottom
PR70  100KR2F-L1-GP  [R402H16]  216.08 229.06 270 bottom
PR71  10R2J-2-GP  [R402H14]  197.26 171.22 0 bottom
PR72  GAP-CLOSE-PWR-3-GP  [GAP-CLOSE-PWR-3]  216.66 224.94 270 top
PR73  499R2F-2-GP  [R402H16]  217.42 230.17 270 bottom
PR74  41K2R2F-GP  [R402H16]  214.96 223.77 0 top
PR75  2K61R2F-1-GP  [R402H16]  221.26 227.46 180 top
PR76  11KR2F-L-GP  [R402H16]  219.53 226.47 90 top
PR77  NTC-100K-12-GP-U  [NTC-402H22-U]  207.49 168.22 180 top
PR78  10KR2F-2-GP  [R402H16]  215.95 227.23 270 top
PR79  787R2F-GP  [R402H16]  220.83 227.33 180 bottom
PR80  100R2F-L1-GP-U  [R402H14]  219.25 227.66 270 bottom
PR81  41K2R2F-GP  [R402H16]  213.94 223.77 0 top
PR82  27K4R2F-GP  [R402H16]  221.92 221.28 90 top
PR83  2D2R5J-1-GP  [R805H24]  208.13 222 90 top
PR84  10KR2F-2-GP  [R402H16]  222.71 224.87 180 top
PR85  0R0402-PAD-2-GP  [0R0402-PAD-1]  221.92 220.17 90 bottom
PR86  0R0402-PAD-2-GP  [0R0402-PAD-1]  221.97 220.19 270 top
PR87  0R0402-PAD-2-GP  [0R0402-PAD-1]  221.97 219.13 90 bottom
PR88  NTC-100K-12-GP-U  [NTC-402H22-U]  207.7 196.67 90 top
PR89  133KR2F-GP  [R402H16]  217.25 221.72 270 top
PR90  0R0402-PAD-2-GP  [0R0402-PAD-1]  221.82 218.97 270 top
PR91  33R2J-2-GP  [R402H16]  221.84 217.96 270 top
PR92  2D2R5J-1-GP  [R805H24]  209.7 216.1 270 top
PR94  0R0402-PAD-2-GP  [0R0402-PAD-1]  221.92 216.87 270 top
PR95  18K2R2F-L-GP  [R402H16]  224.18 220.52 0 top
PR96  0R0402-PAD-2-GP  [0R0402-PAD-1]  221.89 216.81 90 bottom
PR97  27K4R2F-GP  [R402H16]  221.89 215.8 270 bottom
PR98  133KR2F-GP  [R402H16]  217.27 217.63 270 top
PR99  NTC-100K-12-GP-U  [NTC-402H22-U]  203.89 212.52 180 top
PR100  18K2R2F-L-GP  [R402H16]  221.59 213.33 270 top
PR101  100KR2F-L1-GP  [R402H16]  211.2 213.87 90 top
PR102  0R2J-2-GP  [R402H16]  219.13 215.6 90 top
PR103  1KR2F-3-GP  [R402H16]  212.55 212.32 0 top
PR104  0R2J-2-GP  [R402H16]  219.13 214.45 90 top
PR105  100KR2F-L1-GP  [R402H16]  209.93 212.47 90 top
PR106  1K62R2F-GP  [R402H16]  213.84 212.9 90 bottom
PR107  3K57R2F-GP  [R402H16]  211.53 212.37 180 top
PR108  32K4R2F-1-GP  [R402H16]  212.98 216.61 180 top
PR109  2K61R2F-1-GP  [R402H16]  215.77 212.67 180 bottom
PR110  10R2J-2-GP  [R402H14]  213.33 209.07 270 bottom
PR111  11KR2F-L-GP  [R402H16]  217.5 213.06 0 top
PR112  GAP-CLOSE-PWR-3-GP  [GAP-CLOSE-PWR-3]  214.43 210.34 270 bottom
PR113  NTC-100K-12-GP-U  [NTC-402H22-U]  203.5 206.4 180 top
PR114  GAP-CLOSE-PWR-3-GP  [GAP-CLOSE-PWR-3]  213.54 211.02 270 top
PR115  10R2J-2-GP  [R402H14]  214.05 209.73 90 top
PR116  768R2F-1-GP  [R402H16]  215.34 212.75 0 top
PR117  100R2F-L1-GP-U  [R402H14]  218.97 212.47 90 top
PR118  1R5J-2-GP  [R805H24]  187.63 209.35 180 bottom
PR119  22KR2J-GP  [R402H16]  189.61 210.16 270 bottom
PR120  2D2R5J-1-GP  [R805H24]  209.83 211.71 270 bottom
PR121  2D2R6J-3-GP  [R1206H28]  195.4 213.89 180 top
PR122  10KR2F-2-GP  [R402H16]  207.87 208.79 0 top
PR123  10KR2F-2-GP  [R402H16]  206.81 208.79 0 top
PR124  10R2F-L-GP  [R402H14]  205.77 208.79 0 top
PR125  3K65R5F-GP  [R805H24]  209.45 208.48 180 top
PR126  10KR2F-2-GP  [R402H16]  210.97 209.09 0 top
PR127  1R5J-2-GP  [R805H24]  170.69 209.55 180 bottom
PR128  2D2R5J-1-GP  [R805H24]  206.88 224.03 270 bottom
PR129  2D2R6J-3-GP  [R1206H28]  178.94 214.15 180 top
PR130  22KR2J-GP  [R402H16]  172.62 210.24 270 bottom
PR131  10KR2F-2-GP  [R402H16]  206.86 205.64 0 top
PR132  10KR2F-2-GP  [R402H16]  207.87 205.64 0 top
PR133  10R2F-L-GP  [R402H14]  205.84 205.64 0 top
PR134  3K65R5F-GP  [R805H24]  209.42 204.9 0 top
PR135  10KR2F-2-GP  [R402H16]  210.95 204.22 180 top
PR136  1R5J-2-GP  [R805H24]  155.73 208.71 180 bottom
PR137  2D2R5J-1-GP  [R805H24]  208.48 227.23 180 bottom
PR138  2D2R6J-3-GP  [R1206H28]  162.61 214.02 180 top
PR139  22KR2J-GP  [R402H16]  157.66 210.11 270 bottom
PR140  10KR2F-2-GP  [R402H16]  206.83 202.1 0 top
PR141  10KR2F-2-GP  [R402H16]  208.08 202.08 0 top
PR142  10R2F-L-GP  [R402H14]  205.79 202.08 0 top
PR143  3K65R5F-GP  [R805H24]  208.38 200.13 270 top
PR144  10KR2F-2-GP  [R402H16]  209.63 201.7 270 top
PR145  2D2R5J-1-GP  [R805H24]  214.96 205.77 270 top
PR146  2D2R5J-1-GP  [R805H24]  218.06 202.46 0 top
PR147  1R5J-2-GP  [R805H24]  211.66 198.78 180 bottom
PR148  22KR2J-GP  [R402H16]  207.82 195.4 270 top
PR149  2D2R6J-3-GP  [R1206H28]  211.84 189.23 90 top
PR150  10KR2F-2-GP  [R402H16]  221.11 223.01 0 top
PR151  10R2F-L-GP  [R402H14]  222.2 222.99 0 top
PR152  3K65R5F-GP  [R805H24]  222.02 223.77 180 bottom
PR153  10KR2F-2-GP  [R402H16]  220.5 223.88 180 bottom
PR154  2D2R5J-1-GP  [R805H24]  223.42 201.96 270 top
PR155  2D2R5J-1-GP  [R805H24]  221.49 208.33 90 top
PR156  1R5J-2-GP  [R805H24]  225.63 189.08 270 bottom
PR157  22KR2J-GP  [R402H16]  229.11 189.13 270 bottom
PR158  2D2R6J-3-GP  [R1206H28]  228.02 189.31 270 top
PR159  10KR2F-2-GP  [R402H16]  224.03 222.94 180 bottom
PR160  10R2F-L-GP  [R402H14]  225.15 222.91 180 bottom
PR161  3K65R5F-GP  [R805H24]  224.82 223.27 0 top
PR162  10KR2F-2-GP  [R402H16]  223.27 222.96 0 top
PR163  5D1R2F-GP  [R402H16]  219.58 140.08 270 top
PR164  -  [0R0603-PAD]  216.94 140.06 180 top
PR165  174KR2F-GP  [R402H16]  219.51 138.38 270 top
PR166  10KR2F-2-GP  [R402H16]  219.84 142.49 0 top
PR167  2D2R3-1-U-GP  [R603H22]  223.37 134.95 270 top
PR168  750KR2F-GP  [R402H16]  220.98 144.15 90 top
PR169  2D2R5F-2-GP  [R805H24]  224.04 121.6 180 top
PR170  15K8R2F-GP  [R402H16]  226.42 143 270 top
PR171  20KR2F-L-GP  [R402H16]  228.27 145.47 180 top
PR172  0R0402-PAD-2-GP  [0R0402-PAD-1]  223.9 144.15 90 top
PR174  0R0402-PAD-2-GP  [0R0402-PAD-1]  227.69 147.02 270 top
PR184  95K3R2F-GP  [R402H16]  149.73 218.69 90 bottom
PR185  3K83R2F-GP  [R402H16]  143.38 217.7 180 bottom
PR186  100KR2F-L1-GP  [R402H16]  145.62 215.8 180 top
PR187  30KR2F-GP  [R402H16]  145.39 217.78 0 bottom
PR188  2D2R3-1-U-GP  [R603H22]  143.08 18.54 270 top
PR189  16K9R2F-GP  [R402H16]  150.98 20.35 270 top
PR190  22K1R2F-L-GP  [R402H16]  151.43 18.06 90 top
PR191  0R2J-2-GP  [R402H16]  150.42 19.48 270 bottom
PR192  1MR2F-GP  [R402H16]  151.41 16 90 top
PR193  2D2R3-1-U-GP  [R603H22]  130.68 109.63 270 top
PR194  44K2R2F-1-GP  [R402H16]  138.81 114.17 0 top
PR195  22K1R2F-L-GP  [R402H16]  139.27 108.84 0 top
PR196  0R2J-2-GP  [R402H16]  138.94 104.6 90 top
PR197  1MR2F-GP  [R402H16]  139.19 106.3 270 bottom
PR198  2D2R5J-1-GP  [R805H24]  15.01 196.29 90 bottom
PR199  2D2R3-1-U-GP  [R603H22]  11.68 201.52 90 bottom
PR200  2D2R5J-1-GP  [R805H24]  14.25 196.04 180 top
PR201  0R0402-PAD-2-GP  [0R0402-PAD-1]  7.21 196.52 0 top
PR202  1KR2F-3-GP  [R402H16]  6.38 198.55 0 bottom
PR203  100KR2F-L1-GP  [R402H16]  7.49 198.55 0 bottom
PR204  5K23R2F-GP  [R402H16]  7.32 201.78 0 bottom
PR206  47K5R2F-GP  [R402H16]  139.19 75.13 90 top
PR207  10KR2F-2-GP  [R402H16]  141.6 65.13 270 top
PR208  22K1R2F-L-GP  [R402H16]  141.6 74.68 0 top
PR209  0R0402-PAD-2-GP  [0R0402-PAD-1]  146.35 65.25 270 top
PR210  0R2J-2-GP  [R402H16]  130.73 122.66 90 top
PR212  10KR2F-L1-GP  [R402H15]  130.66 127.05 90 top
PR214  0R2F-1-GP  [R402H16]  128.12 126.16 90 top
PR215  3K9R2F-GP  [R402H16]  124.84 211.46 270 top
PR216  10KR2F-2-GP  [R402H16]  131.95 213.36 270 top
PR217  3KR2F-GP  [R402H16]  124.97 210.31 90 top
PR218  0R0402-PAD-2-GP  [0R0402-PAD-1]  124.33 216.41 90 top
PR219  33KR2F-GP  [R402H16]  103.84 89.74 0 top
PR220  33KR2F-GP  [R402H16]  103.78 87.73 270 top
PR221  2D2R3J-2-GP  [R603H22]  111.96 155.68 90 top
PR223  2KR2F-3-GP  [R402H16]  116.38 138.78 180 top
PR224  2KR2F-3-GP  [R402H16]  115.29 138.17 180 top
PR225  2KR2F-3-GP  [R402H16]  114.15 138.17 180 top
PR228  75R2F-2-GP  [R402H16]  105.51 146.07 90 top
PR229  56R2F-1-GP  [R402H16]  105.69 148.18 90 top
PR230  10KR2F-2-GP  [R402H16]  105.71 149.25 90 top
PR231  2K2R2J-2-GP  [R402H16]  111.91 139.04 180 top
PR232  100KR2F-L1-GP  [R402H16]  112.19 146 0 bottom
PR233  52K3R2F-L-GP  [R402H16]  117.35 141.99 0 top
PR234  10KR2F-2-GP  [R402H16]  115.24 146 0 bottom
PR235  0R0402-PAD-2-GP  [0R0402-PAD-1]  111.3 144.48 270 bottom
PR236  0R0402-PAD-2-GP  [0R0402-PAD-1]  113.18 142.57 0 top
PR237  0R0402-PAD-2-GP  [0R0402-PAD-1]  108.18 147.83 270 top
PR238  0R0402-PAD-2-GP  [0R0402-PAD-1]  108.18 145.8 270 top
PR239  0R0402-PAD-2-GP  [0R0402-PAD-1]  107.9 144.76 270 top
PR240  0R0402-PAD-2-GP  [0R0402-PAD-1]  109.98 141.94 270 top
PR242  1K5R2F-2-GP  [R402H16]  120.5 144.65 270 top
PR243  0R0402-PAD-2-GP  [0R0402-PAD-1]  108.18 146.81 270 top
PR244  1K5R2F-2-GP  [R402H16]  125.78 141.53 0 top
PR245  0R0402-PAD-2-GP  [0R0402-PAD-1]  114.27 141.99 0 top
PR246  0R0402-PAD-2-GP  [0R0402-PAD-1]  115.29 141.99 0 top
PR247  0R0402-PAD-2-GP  [0R0402-PAD-1]  116.3 141.99 0 top
PR248  1K5R2F-2-GP  [R402H16]  125.6 146.79 0 top
PR249  180R2F-1-GP  [R402H16]  115.91 156.35 90 top
PR250  1K5R2F-2-GP  [R402H16]  124.13 150.47 0 top
PR251  100R2J-2-GP  [R402H14]  114.45 158.85 270 bottom
PR252  0R0402-PAD-2-GP  [0R0402-PAD-1]  118.31 155.7 270 bottom
PR253  0R0402-PAD-2-GP  [0R0402-PAD-1]  115.6 155.32 90 top
PR254  0R0402-PAD-2-GP  [0R0402-PAD-1]  119.1 154.23 180 top
PR255  1K5R2F-2-GP  [R402H16]  125.22 153.92 0 top
PR256  100R2J-2-GP  [R402H14]  118.09 154.56 180 top
PR257  1K5R2F-2-GP  [R402H16]  125.58 157.86 90 top
PR258  180R2F-1-GP  [R402H16]  114.2 146 180 bottom
PR259  1K5R2F-2-GP  [R402H16]  121.21 153.95 270 bottom
PR260  100R2J-2-GP  [R402H14]  119 139.65 180 top
PR261  0R0402-PAD-2-GP  [0R0402-PAD-1]  117.45 137.82 180 top
PR262  0R0402-PAD-2-GP  [0R0402-PAD-1]  118.36 141.99 0 top
PR263  0R0402-PAD-2-GP  [0R0402-PAD-1]  120.3 142.01 0 top
PR264  100R2J-2-GP  [R402H14]  120.98 139.7 0 top
PR265  0R0402-PAD-2-GP  [0R0402-PAD-1]  115.62 155.55 270 bottom
PR266  0R0402-PAD-2-GP  [0R0402-PAD-1]  114.1 155.19 180 bottom
PR267  0R0402-PAD-2-GP  [0R0402-PAD-1]  111.89 155.14 180 bottom
PR268  0R0402-PAD-2-GP  [0R0402-PAD-1]  113.08 155.19 180 bottom
PR271  2D2R5J-1-GP  [R805H24]  103.3 123.93 90 top
PR272  2D2R5J-1-GP  [R805H24]  66.5 123.83 90 top
PR273  0R0402-PAD-2-GP  [0R0402-PAD-1]  95.4 121.05 0 top
PR274  0R0402-PAD-2-GP  [0R0402-PAD-1]  58.29 121.28 0 top
PR275  -  [0R0603-PAD]  97.38 117.14 90 bottom
PR276  -  [0R0603-PAD]  60.34 117.17 90 bottom
PR277  0R0402-PAD-2-GP  [0R0402-PAD-1]  97.18 121.06 180 bottom
PR278  0R0402-PAD-2-GP  [0R0402-PAD-1]  59.99 122.58 90 bottom
PR279  0R0402-PAD-2-GP  [0R0402-PAD-1]  95.95 124.01 270 top
PR280  0R0402-PAD-2-GP  [0R0402-PAD-1]  59.26 124.06 180 top
PR281  0R0402-PAD-2-GP  [0R0402-PAD-1]  99.59 123.42 90 bottom
PR282  0R0402-PAD-2-GP  [0R0402-PAD-1]  64.29 123.77 0 bottom
PR285  2D2R5J-1-GP  [R805H24]  91.29 123.8 90 top
PR286  2D2R5J-1-GP  [R805H24]  54.66 123.83 90 top
PR287  0R0402-PAD-2-GP  [0R0402-PAD-1]  47.39 121.07 0 top
PR288  0R0402-PAD-2-GP  [0R0402-PAD-1]  83.74 121.3 0 top
PR289  -  [0R0603-PAD]  49.22 117.17 90 bottom
PR290  -  [0R0603-PAD]  85.84 117.14 90 bottom
PR291  0R0402-PAD-2-GP  [0R0402-PAD-1]  50.47 121.39 90 bottom
PR292  0R0402-PAD-2-GP  [0R0402-PAD-1]  86.13 121.11 90 bottom
PR293  0R0402-PAD-2-GP  [0R0402-PAD-1]  47.36 124.36 270 top
PR294  0R0402-PAD-2-GP  [0R0402-PAD-1]  84.24 124.14 270 top
PR295  0R0402-PAD-2-GP  [0R0402-PAD-1]  87.2 123.34 90 bottom
PR296  0R0402-PAD-2-GP  [0R0402-PAD-1]  53.29 122.88 270 bottom
PR299  2D2R5J-1-GP  [R805H24]  80.19 123.8 90 top
PR300  2D2R5J-1-GP  [R805H24]  43.56 123.83 90 top
PR301  0R0402-PAD-2-GP  [0R0402-PAD-1]  72.26 121.78 0 top
PR302  0R0402-PAD-2-GP  [0R0402-PAD-1]  35.5 121.96 0 top
PR303  -  [0R0603-PAD]  74.95 117.14 90 bottom
PR304  -  [0R0603-PAD]  38.12 117.17 90 bottom
PR305  0R0402-PAD-2-GP  [0R0402-PAD-1]  73.99 121.18 90 bottom
PR306  0R0402-PAD-2-GP  [0R0402-PAD-1]  37.59 121.06 90 bottom
PR307  0R0402-PAD-2-GP  [0R0402-PAD-1]  73.67 124.04 180 top
PR308  0R0402-PAD-2-GP  [0R0402-PAD-1]  37.04 124.06 180 top
PR309  0R0402-PAD-2-GP  [0R0402-PAD-1]  77.42 123.32 0 bottom
PR310  0R0402-PAD-2-GP  [0R0402-PAD-1]  41.73 121.84 270 bottom
PR312  2D2R5J-1-GP  [R805H24]  133.93 225.98 180 top
PR313  0R0402-PAD-2-GP  [0R0402-PAD-1]  136.24 215.85 0 top
PR314  -  [0R0603-PAD]  139.98 215.87 0 bottom
PR315  0R0402-PAD-2-GP  [0R0402-PAD-1]  136.78 218.95 180 bottom
PR316  0R0402-PAD-2-GP  [0R0402-PAD-1]  135.17 215.82 0 top
PR317  0R0402-PAD-2-GP  [0R0402-PAD-1]  135.51 218.95 180 bottom
PR318  2D2R3-1-U-GP  [R603H22]  111.76 202.72 180 bottom
PR319  28K7R2F-GP  [R402H16]  119.23 206.1 90 bottom
PR320  0R0402-PAD-2-GP  [0R0402-PAD-1]  119.33 211.18 90 bottom
PR321  1MR2F-GP  [R402H16]  117.86 210.77 0 bottom
PR322  56K2R2F-2-GP  [R402H16]  120.24 208.05 270 bottom
PR323  0R2J-2-GP  [R402H16]  119.63 209.52 0 bottom
PR324  100KR2F-L1-GP  [R402H16]  115.6 211.4 180 bottom
PR325  0R2J-2-GP  [R402H16]  119.28 207.72 90 top
PR326  0R0402-PAD-2-GP  [0R0402-PAD-1]  117.4 212.65 90 bottom
PR327  750KR2F-GP  [R402H16]  10.59 207.39 0 bottom
PR328  26K7R2F-GP  [R402H16]  6.55 209.63 0 top
PR330  20KR2F-L-GP  [R402H16]  6.63 207.67 0 top
PR333  10KR2F-2-GP  [R402H16]  144.37 213.13 0 top
PR334  0R0402-PAD-2-GP  [0R0402-PAD-1]  145.87 212.7 270 top
PR335  10KR2F-2-GP  [R402H16]  148.36 13.72 270 top
PR336  0R0402-PAD-2-GP  [0R0402-PAD-1]  145.01 13.44 270 bottom
PR337  0R0402-PAD-2-GP  [0R0402-PAD-1]  151.1 13.23 180 top
PR338  10KR2F-2-GP  [R402H16]  136.42 104.55 180 top
PR339  0R0402-PAD-2-GP  [0R0402-PAD-1]  135.3 104.52 180 top
PR340  1KR2J-1-GP  [R402H16]  137.16 105.79 270 bottom
PR341  10KR2F-2-GP  [R402H16]  7.19 198.67 0 top
PR342  0R2F-1-GP  [R402H16]  8.21 198.68 0 top
PR344  10KR2F-2-GP  [R402H16]  107.89 143.74 90 top
PR345  0R2J-2-GP  [R402H16]  107.91 142.67 270 top
PR346  10KR2F-2-GP  [R402H16]  12.14 207.39 180 top
PR347  0R0402-PAD-2-GP  [0R0402-PAD-1]  11.07 207.39 0 top
PR348  0R0402-PAD-2-GP  [0R0402-PAD-1]  151.41 17.02 90 top
PR349  0R0402-PAD-2-GP  [0R0402-PAD-1]  139.17 107.29 90 top
PR350  20KR2F-L-GP  [R402H16]  147.35 216.71 180 bottom
PR352  2K8R2F-GP  [R402H16]  145.67 204.98 0 top
PR354  22K1R2F-L-GP  [R402H16]  144.12 203.28 270 top
PR355  0R2J-2-GP  [R402H16]  143.28 213.13 0 top
PR359  19K6R2F-GP  [R402H16]  141.07 127.69 90 top
PR360  22K1R2F-L-GP  [R402H16]  141.45 125.91 0 top
PR361  10KR2F-L1-GP  [R402H15]  143.66 216.26 180 top
PR362  0R0402-PAD-2-GP  [0R0402-PAD-1]  146.76 216.92 0 top
PR363  10KR2F-L1-GP  [R402H15]  149.99 13.21 180 top
PR374  10KR2F-2-GP  [R402H16]  107.65 161.46 270 top
PR375  1KR2J-1-GP  [R402H16]  107.15 163.66 270 top
PR376  27K4R2F-GP  [R402H16]  96.81 160.82 180 top
PR377  21K5R2F-GP  [R402H16]  95.31 162.34 270 top
PR378  0R0402-PAD-2-GP  [0R0402-PAD-1]  107.02 162.6 90 top
PR384  100KR2F-L1-GP  [R402H16]  147.83 216.89 180 top
PR386  100KR2F-L1-GP  [R402H16]  7.6 196.34 0 bottom
PR387  100KR2F-L1-GP  [R402H16]  143.98 64.85 0 top
PR388  100KR2F-L1-GP  [R402H16]  132.59 55.75 0 top
PR389  100KR2F-L1-GP  [R402H16]  130.73 124.69 270 top
PR390  100KR2F-L1-GP  [R402H16]  105.24 162.59 270 bottom
PR391  100KR2F-L1-GP  [R402H16]  9.08 207.67 90 bottom
PR392  10KR2F-L1-GP  [R402H15]  9.39 206.16 180 top
PR393  0R0402-PAD-2-GP  [0R0402-PAD-1]  9.08 207.67 270 top
PR394  10KR2F-2-GP  [R402H16]  141.53 213.97 270 bottom
PR395  10KR2F-L1-GP  [R402H15]  128.35 58.78 90 top
PR396  1KR2J-1-GP  [R402H16]  133.6 54.48 180 top
PR397  47K5R2F-GP  [R402H16]  138.51 59.94 0 top
PR398  22K1R2F-L-GP  [R402H16]  137.67 57.91 0 top
PR399  0R0402-PAD-2-GP  [0R0402-PAD-1]  214.12 130.43 270 top
PR400  0R0402-PAD-2-GP  [0R0402-PAD-1]  177.9 53.09 180 top
PR404  0R0402-PAD-2-GP  [0R0402-PAD-1]  8.18 206.17 180 top
PR405  0R0402-PAD-2-GP  [0R0402-PAD-1]  112.03 142.55 0 top
PR406  2K2R2J-2-GP  [R402H16]  112.93 139.03 180 top
PR410  D001R2512F-11-GP-U  [R2512-27D4-4PH28]  29.03 109.55 180 top
PR412  2D2R5J-1-GP  [R805H24]  106.65 33.05 180 bottom
PR413  0R2J-2-GP  [R402H16]  123.51 152.18 90 top
PR414  0R2J-2-GP  [R402H16]  120.75 149.56 0 top
PR415  0R2J-2-GP  [R402H16]  122.35 148.05 180 top
PR416  0R2J-2-GP  [R402H16]  122.35 146.16 0 top
PR417  0R2J-2-GP  [R402H16]  122.7 144.7 90 top
PR418  0R2J-2-GP  [R402H16]  122.71 142.55 0 top
PR419  0R0402-PAD-2-GP  [0R0402-PAD-1]  106.3 141.3 90 top
PR420  100KR2F-L1-GP  [R402H16]  12 142.62 180 bottom
PR421  2D2R3-1-U-GP  [R603H22]  8.99 215.98 180 top
PR422  2D2R5F-2-GP  [R805H24]  22.91 217.35 270 top
PR423  -  [0R0603-PAD]  14.94 209.5 90 top
PR424  5D1R2F-GP  [R402H16]  14.78 208.25 90 top
PR425  215KR2F-GP  [R402H16]  14.05 210.64 270 bottom
PT1  ST330U6VDM-2-GP  [CT7343H75]  221.77 36.02 0 top
PT2  ST330U6VDM-2-GP  [CT7343H75]  224.41 43.61 90 top
PT3  SE220U6D3VM-42-GP  [SE361416H182]  133.6 23.06 180 top
PT5  SE220U6D3VM-42-GP  [SE361416H182]  133.6 32.49 0 top
PT6  SE47U25VM-13-GP  [SE361414H241]  194.21 223.6 90 top
PT7  E820U2D5VM-6-GP  [ECAP-100D6D3H375]  197.51 196.09 90 top
PT8  E820U2D5VM-6-GP  [ECAP-100D6D3H375]  190.12 193.52 90 top
PT11  E820U2D5VM-6-GP  [ECAP-100D6D3H375]  175.34 193.34 90 top
PT12  E820U2D5VM-6-GP  [ECAP-100D6D3H375]  182.68 196.06 90 top
PT14  SE47U25VM-13-GP  [SE361414H241]  162.86 224.21 90 top
PT15  E820U2D5VM-6-GP  [ECAP-100D6D3H375]  159.99 195.83 90 top
PT16  E820U2D5VM-6-GP  [ECAP-100D6D3H375]  167.87 195.94 90 top
PT17  E820U2D5VM-6-GP  [ECAP-100D6D3H375]  204.06 163.12 0 top
PT18  E820U2D5VM-6-GP  [ECAP-100D6D3H375]  203.96 172.82 0 top
PT19  E820U2D5VM-6-GP  [ECAP-100D6D3H375]  222 163.07 0 top
PT20  E820U2D5VM-6-GP  [ECAP-100D6D3H375]  214.12 163.07 0 top
PT21  SE560U2D5VM-1-GP  [SE361416H237]  227.2 97.41 0 top
PT25  SE47U25VM-13-GP  [SE361414H241]  97.03 110.49 270 top
PT27  SE47U25VM-13-GP  [SE361414H241]  77.01 110.34 90 top
PT28  SE47U25VM-13-GP  [SE361414H241]  64.87 110.41 90 top
PT29  E820U2D5VM-6-GP  [ECAP-100D6D3H375]  100.69 142.6 0 top
PT30  E820U2D5VM-6-GP  [ECAP-100D6D3H375]  68.33 143.89 0 top
PT32  E820U2D5VM-6-GP  [ECAP-100D6D3H375]  92.81 142.7 0 top
PT33  E820U2D5VM-6-GP  [ECAP-100D6D3H375]  84.61 142.7 0 top
PT35  E820U2D5VM-6-GP  [ECAP-100D6D3H375]  43.69 150.75 0 top
PT38  E820U2D5VM-6-GP  [ECAP-100D6D3H375]  76.61 142.67 0 top
PT39  E820U2D5VM-6-GP  [ECAP-100D6D3H375]  43.59 142.6 0 top
PT41  SE47U25VM-13-GP  [SE361414H241]  146.86 223.7 180 top
PT42  E560U6D3VM-3-GP  [ECAP-100D6D3H375]  108.81 219 90 top
PT43  E820U2D5VM-6-GP  [ECAP-100D6D3H375]  108.79 211.18 90 top
PT44  SE330U2VDM-4-GP  [CT7343H83]  32.87 219.42 180 top
PU1  SM4378NSKPC-TRG-GP  [PPAK-8PH48]  115.7 38.15 270 bottom
PU2  SM4378NSKPC-TRG-GP  [PPAK-8PH48]  115.67 13.94 270 bottom
PU3  RT6575DGQW-GP  [QFN20-G1D75H32]  102.62 30.76 90 top
PU4  SM4504NHKPC-TRG-1-GP  [PPAK-8PH48]  117.45 22.68 90 bottom
PU5  SM4504NHKPC-TRG-1-GP  [PPAK-8PH48]  117.45 29.49 90 bottom
PU6  ISL62773AHRZ-T-GP  [QFN48J6-G4D55H40]  214.5 219.61 90 bottom
PU7  TPH6R003NL-GP  [PPAK-8P-1-UH40]  190.73 216.41 180 bottom
PU8  TPH6R003NL-GP  [PPAK-8P-1-UH40]  190.73 216.41 0 top
PU9  TPCA8059-H-GP  [PPAK-8P-1-UH40]  199.87 214.6 0 bottom
PU10  TPCA8059-H-GP  [PPAK-8P-1-UH40]  199.87 214.6 180 top
PU11  TPH6R003NL-GP  [PPAK-8P-1-UH40]  174.55 216.41 0 top
PU12  TPH6R003NL-GP  [PPAK-8P-1-UH40]  174.55 216.41 180 bottom
PU13  TPCA8059-H-GP  [PPAK-8P-1-UH40]  183.49 214.4 180 top
PU14  TPCA8059-H-GP  [PPAK-8P-1-UH40]  183.49 214.4 0 bottom
PU15  TPH6R003NL-GP  [PPAK-8P-1-UH40]  158.19 216.23 0 top
PU16  TPH6R003NL-GP  [PPAK-8P-1-UH40]  158.19 216.23 180 bottom
PU17  TPCA8059-H-GP  [PPAK-8P-1-UH40]  167.03 214.6 180 top
PU18  TPCA8059-H-GP  [PPAK-8P-1-UH40]  167.03 214.6 0 bottom
PU19  TPH6R003NL-GP  [PPAK-8P-1-UH40]  214.35 193.7 90 bottom
PU20  TPH6R003NL-GP  [PPAK-8P-1-UH40]  214.35 193.7 270 top
